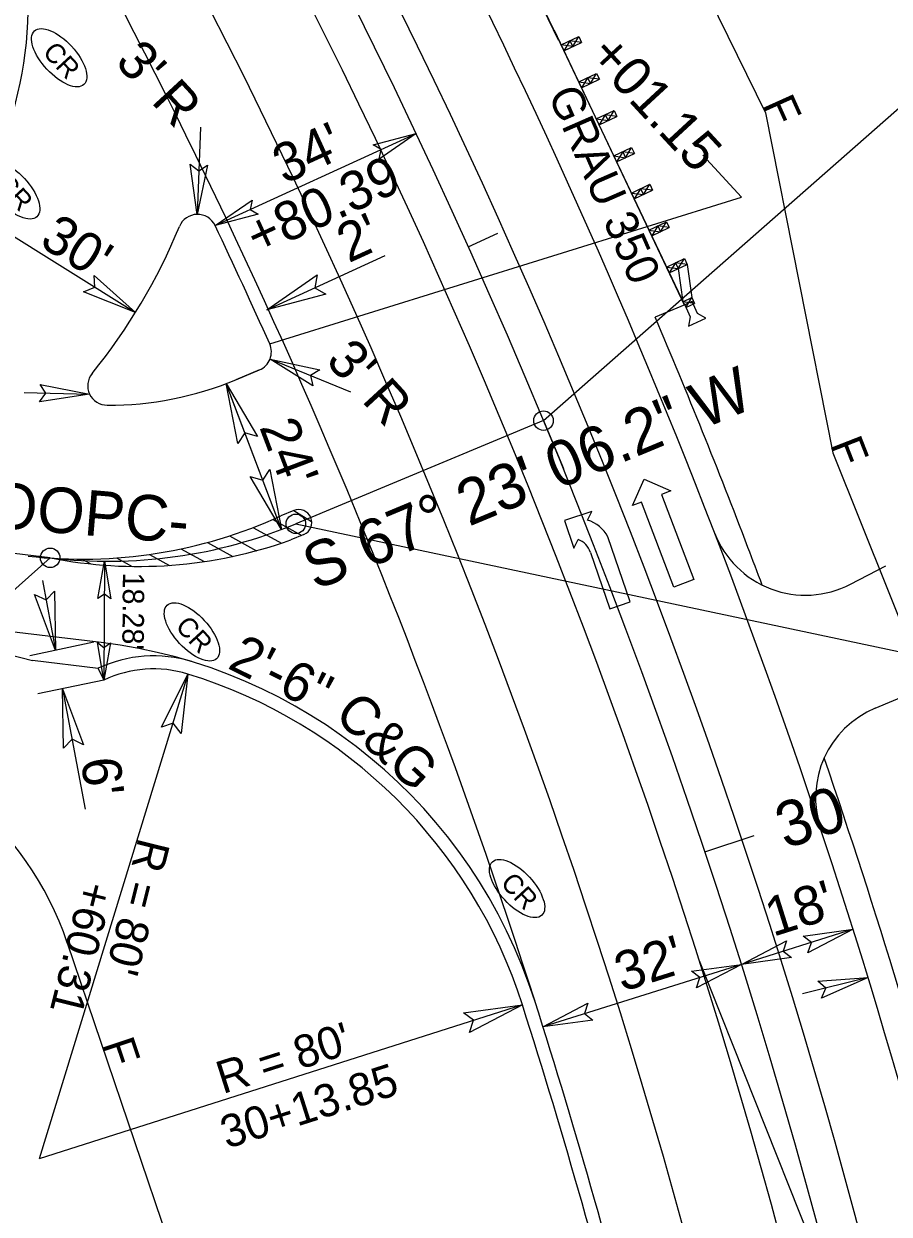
# Model space of a CAD drawing. Extents: x 1702862 to 1704514, y 793768 to 796215.
# Drawn here: x 1703832.7 to 1703965.8, y 794386.1 to 794569.2 of the extents above; entities that cross this region are included whole.
import ezdxf

# ---------------------------------------------------------------- set-up
doc = ezdxf.new("R2010")
doc.units = 0
for name, color, linetype in [('Prop Conc 2ft 6in Curb and Gutter', 7, 'Continuous'), ('Prop Conc 5in Monolithic Surface Mount Island', 7, 'Continuous'), ('Prop Dimension', 7, 'Continuous'), ('Prop Dimension Text', 7, 'Continuous'), ('Prop DSN Text', 7, 'Continuous'), ('Prop EOT', 7, 'Continuous'), ('Prop Guardrail', 7, 'Continuous'), ('Prop Guardrail Anchor Unit CELL', 7, 'Continuous'), ('Prop Horizontal Alignment', 7, 'Continuous'), ('Prop Horizontal Alignment Direction Label', 7, 'Continuous'), ('Prop Horizontal Alignment Station Label', 7, 'Continuous'), ('Prop Horizontal Alignment Tick Label', 7, 'Continuous'), ('Prop Horizontal Alignment Tick Large', 7, 'Continuous'), ('Prop Horizontal Alignment Tick Small', 7, 'Continuous'), ('Prop Lane Arrow CELL', 7, 'Continuous'), ('Prop Lane Lines', 7, 'Continuous'), ('Prop Paint Stripe', 7, 'Continuous'), ('Prop Paved Shoulder', 7, 'Continuous'), ('Prop SS Fill Line', 7, 'Continuous'), ('Prop SS Misc', 7, 'Continuous'), ('Prop SS Transition Line', 7, 'Continuous'), ('Prop Terminator CELL', 7, 'Continuous'), ('Prop WCR CELL', 7, 'Continuous')]:
    doc.layers.add(name, color=color, linetype=linetype)

msp = doc.modelspace()

# ---------------------------------------------------------------- linework, layer by layer
at = {"layer": 'Prop Conc 2ft 6in Curb and Gutter'}
for centre, radius, start, end in [((1703852.67, 794451.95), 18, 72.9584, 115.227), ((1703835.09, 794394.58), 78, 17.697, 72.9584), ((1702989.11, 794124.65), 966, 10.14602, 17.69698)]:
    msp.add_arc(centre, radius, start, end, dxfattribs=at)
at = {"layer": 'Prop Conc 5in Monolithic Surface Mount Island'}
for p, q in [((1703865.32, 794514.43), (1703868.95, 794515.94)), ((1703868.95, 794515.94), (1703865.32, 794514.43))]:
    msp.add_line(p, q, dxfattribs=at)
for centre, radius, start, end in [((1703859.42, 794536.86), 3, 25.344, 157.6692), ((1703859.42, 794536.86), 3, 25.344, 157.6692), ((1703773.4, 794572.2), 90, 320.8717, 337.6692), ((1703773.4, 794572.2), 90, 320.8717, 337.6692), ((1702989.11, 794124.65), 966, 24.15464, 25.34397), ((1702989.11, 794124.65), 966, 24.15464, 25.34397), ((1703867.79, 794518.71), 3, 292.6149, 24.1546), ((1703867.79, 794518.71), 3, 292.6149, 24.1546), ((1703845.54, 794513.51), 3, 140.8717, 269.797), ((1703845.54, 794513.51), 3, 140.8717, 269.797), ((1703845.71, 794561.51), 51, 269.797, 292.6149), ((1703845.71, 794561.51), 51, 269.797, 292.6149)]:
    msp.add_arc(centre, radius, start, end, dxfattribs=at)
at = {"layer": 'Prop Dimension'}
for p, q in [((1703859.91, 794553.27), (1703859.35, 794539.86)), ((1703862.14, 794538.14), (1703893.06, 794552.29)), ((1703824.44, 794540.66), (1703849.88, 794524.75)), ((1703870.07, 794525.2), (1703888.3, 794533.54)), ((1703883.01, 794512.54), (1703870.58, 794517.6)), ((1703872.37, 794491.4), (1703863.84, 794513.84)), ((1703832.77, 794512.44), (1703842.83, 794512.22)), ((1703872.37, 794491.4), (1703864.61, 794511.8)), ((1703845.14, 794486.51), (1703845, 794468.23)), ((1703835.58, 794483.54), (1703837.58, 794472.8)), ((1703843.46, 794474.05), (1703833.63, 794471.98)), ((1703857.95, 794469.16), (1703835.09, 794394.58)), ((1703845, 794468.23), (1703834.87, 794466.1)), ((1703960.26, 794429.91), (1703943.09, 794424.51)), ((1703943.09, 794424.51), (1703912.56, 794414.91)), ((1703962.57, 794422.48), (1703952.5, 794420)), ((1703909.4, 794418.29), (1703835.09, 794394.58))]:
    msp.add_line(p, q, dxfattribs=at)
at = {"layer": 'Prop Dimension Text'}
msp.add_line((1703838.68, 794466.9), (1703842.13, 794448.38), dxfattribs=at)
msp.add_lwpolyline([(1703870.53, 794519.93), (1703943.11, 794542.52), (1703937.18, 794548.94)], dxfattribs=at)
at = {"layer": 'Prop EOT'}
for p, q in [((1703844.62, 794474.01), (1703740.76, 794486.48)), ((1703959.85, 794482.97), (1703965.31, 794485.8)), ((1703844.15, 794470.04), (1703845, 794468.23)), ((1703963.67, 794463.92), (1703974.65, 794468.55))]:
    msp.add_line(p, q, dxfattribs=at)
for centre, radius, start, end in [((1702989.11, 794124.65), 1018, 14.75888, 42.70907), ((1703773.4, 794572.2), 60, 278.4921, 15.5759), ((1703952.94, 794496.29), 15, 201.086, 297.4155), ((1703835.09, 794394.58), 80, 17.697, 83.1536), ((1703852.67, 794451.95), 20, 72.9584, 115.227), ((1703969.5, 794450.1), 15, 112.8746, 198.3644), ((1702989.11, 794124.65), 968, 10.14602, 17.69698)]:
    msp.add_arc(centre, radius, start, end, dxfattribs=at)
at = {"layer": 'Prop Guardrail'}
msp.add_arc((1702988.97, 794124.56), 1026.16, 25.61718, 37.4674, dxfattribs=at)
at = {"layer": 'Prop Guardrail Anchor Unit CELL'}
for p, q in [((1703914.27, 794568.21), (1703934.3, 794525.97)), ((1703915.36, 794565.92), (1703918.07, 794567.2)), ((1703915.36, 794565.92), (1703915.79, 794565.01)), ((1703917.14, 794565.66), (1703915.36, 794565.92)), ((1703916.72, 794566.56), (1703915.79, 794565.01)), ((1703915.79, 794565.01), (1703918.5, 794566.3)), ((1703916.72, 794566.56), (1703917.14, 794565.66)), ((1703918.5, 794566.3), (1703916.72, 794566.56)), ((1703917.14, 794565.66), (1703918.07, 794567.2)), ((1703918.07, 794567.2), (1703918.5, 794566.3)), ((1703915.79, 794565.01), (1703917.14, 794565.66)), ((1703918.06, 794560.22), (1703920.82, 794561.53)), ((1703919.44, 794560.88), (1703918.49, 794559.32)), ((1703918.49, 794559.32), (1703921.25, 794560.63)), ((1703919.44, 794560.88), (1703919.87, 794559.97)), ((1703921.25, 794560.63), (1703919.44, 794560.88)), ((1703919.87, 794559.97), (1703920.82, 794561.53)), ((1703920.82, 794561.53), (1703921.25, 794560.63)), ((1703918.06, 794560.22), (1703919.87, 794559.97)), ((1703920.76, 794554.53), (1703923.51, 794555.83)), ((1703922.14, 794555.18), (1703921.19, 794553.63)), ((1703921.19, 794553.63), (1703923.94, 794554.93)), ((1703922.14, 794555.18), (1703922.57, 794554.28)), ((1703923.94, 794554.93), (1703922.14, 794555.18)), ((1703922.57, 794554.28), (1703923.51, 794555.83)), ((1703923.51, 794555.83), (1703923.94, 794554.93)), ((1703920.76, 794554.53), (1703922.57, 794554.28)), ((1703923.46, 794548.84), (1703926.2, 794550.14)), ((1703924.83, 794549.49), (1703923.89, 794547.93)), ((1703924.83, 794549.49), (1703925.26, 794548.58)), ((1703926.63, 794549.23), (1703924.83, 794549.49)), ((1703925.26, 794548.58), (1703926.2, 794550.14)), ((1703926.2, 794550.14), (1703926.63, 794549.23)), ((1703923.46, 794548.84), (1703923.89, 794547.93)), ((1703923.46, 794548.84), (1703925.26, 794548.58)), ((1703923.89, 794547.93), (1703926.63, 794549.23)), ((1703926.16, 794543.14), (1703928.99, 794544.49)), ((1703927.58, 794543.81), (1703926.59, 794542.24)), ((1703927.58, 794543.81), (1703928.01, 794542.91)), ((1703929.42, 794543.58), (1703927.58, 794543.81)), ((1703928.01, 794542.91), (1703928.99, 794544.49)), ((1703928.99, 794544.49), (1703929.42, 794543.58)), ((1703926.16, 794543.14), (1703928.01, 794542.91)), ((1703926.59, 794542.24), (1703929.42, 794543.58)), ((1703928.86, 794537.45), (1703931.57, 794538.73)), ((1703930.64, 794537.19), (1703931.57, 794538.73)), ((1703931.57, 794538.73), (1703932, 794537.83)), ((1703928.86, 794537.45), (1703930.64, 794537.19)), ((1703930.22, 794538.09), (1703929.29, 794536.54)), ((1703929.29, 794536.54), (1703932, 794537.83)), ((1703930.22, 794538.09), (1703930.64, 794537.19)), ((1703932, 794537.83), (1703930.22, 794538.09)), ((1703931.56, 794531.75), (1703934.33, 794533.07)), ((1703933.37, 794531.51), (1703934.33, 794533.07)), ((1703934.33, 794533.07), (1703934.76, 794532.16)), ((1703931.56, 794531.75), (1703933.37, 794531.51)), ((1703932.94, 794532.41), (1703931.99, 794530.85)), ((1703931.99, 794530.85), (1703934.76, 794532.16)), ((1703932.94, 794532.41), (1703933.37, 794531.51)), ((1703934.76, 794532.16), (1703932.94, 794532.41)), ((1703933.37, 794531.51), (1703934.09, 794526.42)), ((1703934.76, 794532.16), (1703935.44, 794527.07)), ((1703934.09, 794526.42), (1703935.44, 794527.07)), ((1703935.87, 794526.16), (1703934.09, 794526.42)), ((1703934.94, 794526.23), (1703934.38, 794525.97)), ((1703934.38, 794525.97), (1703935.23, 794524.11)), ((1703934.52, 794525.52), (1703935.44, 794527.07)), ((1703934.52, 794525.52), (1703935.87, 794526.16)), ((1703935.5, 794526.48), (1703934.94, 794526.23)), ((1703935.44, 794527.07), (1703935.66, 794526.61)), ((1703935.44, 794527.07), (1703935.87, 794526.16)), ((1703936.34, 794524.61), (1703935.5, 794526.48)), ((1703935.23, 794524.11), (1703934.93, 794522.68)), ((1703934.93, 794522.68), (1703937.61, 794523.89)), ((1703937.61, 794523.89), (1703936.34, 794524.61))]:
    msp.add_line(p, q, dxfattribs=at)
at = {"layer": 'Prop Horizontal Alignment'}
for p, q in [((1703912.65, 794508.14), (1703874.55, 794492.27)), ((1703836.77, 794487.04), (1703719.97, 794501.07))]:
    msp.add_line(p, q, dxfattribs=at)
for centre, radius, start, end in [((1702989.11, 794124.65), 1000, 351.25916, 42.70907), ((1703845.71, 794561.51), 75, 263.1536, 292.6149)]:
    msp.add_arc(centre, radius, start, end, dxfattribs=at)
at = {"layer": 'Prop Horizontal Alignment Station Label'}
for p, q in [((1703912.65, 794508.14), (1704114.85, 794686.06)), ((1703874.55, 794492.27), (1703981.5, 794469.6)), ((1703836.77, 794487.04), (1703754.16, 794413.63))]:
    msp.add_line(p, q, dxfattribs=at)
for centre in [(1703912.65, 794508.14), (1703874.55, 794492.27), (1703836.77, 794487.04)]:
    msp.add_circle(centre, 1.5, dxfattribs=at)
at = {"layer": 'Prop Horizontal Alignment Tick Large'}
for p, q in [((1703912.65, 794508.14), (1703915.73, 794500.76)), ((1703937.48, 794441.8), (1703945.07, 794444.34))]:
    msp.add_line(p, q, dxfattribs=at)
at = {"layer": 'Prop Horizontal Alignment Tick Small'}
msp.add_line((1703901.08, 794534.89), (1703905.64, 794536.95), dxfattribs=at)
at = {"layer": 'Prop Lane Arrow CELL'}
for p, q in [((1703926.33, 794495.09), (1703928.11, 794499.13)), ((1703928.11, 794499.13), (1703932.22, 794497.32)), ((1703932.22, 794497.32), (1703930.82, 794496.79)), ((1703930.82, 794496.79), (1703935.76, 794483.69)), ((1703927.73, 794495.62), (1703926.33, 794495.09)), ((1703932.68, 794482.52), (1703927.73, 794495.62)), ((1703920.08, 794494.17), (1703915.9, 794492.78)), ((1703915.9, 794492.78), (1703917.32, 794488.51)), ((1703919.43, 794492.83), (1703920.08, 794494.17)), ((1703917.32, 794488.51), (1703917.97, 794489.85)), ((1703925.96, 794480.27), (1703922.53, 794490.25)), ((1703919.87, 794487.86), (1703922.84, 794479.2)), ((1703935.76, 794483.69), (1703932.68, 794482.52)), ((1703922.84, 794479.2), (1703925.96, 794480.27))]:
    msp.add_line(p, q, dxfattribs=at)
for centre, radius, start, end in [((1703917.9, 794487.82), 5.25, 27.6389, 72.9506), ((1703916.78, 794486.81), 3.28, 18.9628, 68.621)]:
    msp.add_arc(centre, radius, start, end, dxfattribs=at)
at = {"layer": 'Prop Lane Lines'}
msp.add_line((1703973.28, 794333.07), (1703936.62, 794425.07), dxfattribs=at)
for radius, start, end in [(1006, 0.00687, 42.70907), (994, 359.40932, 42.70907), (980, 359.40932, 42.70907), (968, 17.6382, 31.00789)]:
    msp.add_arc((1702989.11, 794124.65), radius, start, end, dxfattribs=at)
at = {"layer": 'Prop Paint Stripe'}
for p, q in [((1703871.02, 794492.91), (1703875.45, 794490.48)), ((1703874.23, 794494.3), (1703872.25, 794493.48)), ((1703874.22, 794494.3), (1703876.98, 794492.64)), ((1703868.04, 794491.64), (1703872.33, 794489.28)), ((1703860.95, 794489.4), (1703864.87, 794487.25)), ((1703864.36, 794490.41), (1703868.51, 794488.13)), ((1703875.77, 794490.61), (1703873.79, 794489.79)), ((1703846.99, 794487.02), (1703849.37, 794485.72)), ((1703852.02, 794487.56), (1703855.1, 794485.87)), ((1703856.86, 794488.42), (1703860.44, 794486.45)), ((1703841.67, 794486.83), (1703843, 794486.1))]:
    msp.add_line(p, q, dxfattribs=at)
for centre, radius, start, end in [((1703875, 794492.46), 2, 22.6149, 112.6149), ((1703841.63, 794560.61), 73.78, 263.5676, 294.5181), ((1703875, 794492.46), 2, 292.6149, 22.6149), ((1703850.32, 794555.26), 69.55, 258.7681, 289.7186)]:
    msp.add_arc(centre, radius, start, end, dxfattribs=at)
at = {"layer": 'Prop Paved Shoulder'}
for p, q in [((1703914.93, 794566.65), (1703909.49, 794578.04)), ((1703914.26, 794568.23), (1703934.31, 794525.94)), ((1703934.38, 794525.97), (1703929.83, 794524.06)), ((1703803.86, 794478.91), (1703834.03, 794471.26)), ((1703844.15, 794470.04), (1703834.03, 794471.26))]:
    msp.add_line(p, q, dxfattribs=at)
for start, end in [(20.86475, 23.00509), (20.51732, 20.86475), (14.75888, 18.93305)]:
    msp.add_arc((1702989.11, 794124.65), 1022, start, end, dxfattribs=at)
at = {"layer": 'Prop SS Fill Line'}
for p, q in [((1703923.62, 794602.55), (1703946.81, 794555.47)), ((1703946.81, 794555.47), (1703957.17, 794503.16)), ((1703839.4, 794427.8), (1703859.6, 794368.12))]:
    msp.add_line(p, q, dxfattribs=at)
msp.add_arc((1703792.04, 794411.78), 50, 18.6944, 82.73, dxfattribs=at)
at = {"layer": 'Prop SS Transition Line'}
msp.add_line((1703957.17, 794503.16), (1703976.48, 794454.84), dxfattribs=at)
at = {"layer": 'Prop Terminator CELL'}
for points in [[(1703886.44, 794550.54), (1703893.06, 794552.29), (1703887.39, 794548.37), (1703887.67, 794549.82)], [(1703860.98, 794547.45), (1703859.35, 794539.86), (1703858.31, 794547.6), (1703859.63, 794546.57)], [(1703868.76, 794539.89), (1703862.14, 794538.14), (1703867.81, 794542.06), (1703867.52, 794540.61)], [(1703843.51, 794530.44), (1703849.88, 794524.75), (1703841.91, 794527.97), (1703843.61, 794528.66)], [(1703879.15, 794527.6), (1703870.07, 794525.2), (1703877.85, 794530.57), (1703877.46, 794528.58)], [(1703877.17, 794513.5), (1703870.58, 794517.6), (1703878.22, 794515.96), (1703876.8, 794515.07)], [(1703835.21, 794513.7), (1703842.83, 794512.22), (1703835.11, 794511.03), (1703836.12, 794512.37)], [(1703865.64, 794504.62), (1703863.84, 794513.84), (1703868.68, 794505.72), (1703866.73, 794506.24)], [(1703870.57, 794500.62), (1703872.37, 794491.4), (1703867.52, 794499.52), (1703869.48, 794499)], [(1703844.11, 794480.78), (1703845.14, 794486.51), (1703846.12, 794480.73), (1703845.1, 794481.47)], [(1703837.45, 794481.93), (1703837.58, 794472.8), (1703834.35, 794481.41), (1703836.13, 794480.57)], [(1703846.03, 794473.96), (1703845, 794468.23), (1703844.02, 794474.01), (1703845.04, 794473.27)], [(1703853.88, 794460.98), (1703857.95, 794469.16), (1703856.89, 794460.03), (1703855.68, 794461.59)], [(1703838.81, 794457.77), (1703838.68, 794466.9), (1703841.91, 794458.3), (1703840.13, 794459.14)], [(1703952.57, 794428.87), (1703960.26, 794429.91), (1703953.33, 794426.3), (1703953.86, 794427.89)], [(1703950.78, 794425.55), (1703943.09, 794424.51), (1703950.02, 794428.11), (1703949.5, 794426.52)], [(1703935.4, 794423.47), (1703943.09, 794424.51), (1703936.16, 794420.91), (1703936.69, 794422.5)], [(1703954.82, 794421.93), (1703962.57, 794422.48), (1703955.42, 794419.32), (1703956.05, 794420.87)], [(1703900.35, 794417.06), (1703909.4, 794418.29), (1703901.25, 794414.04), (1703901.86, 794415.91)], [(1703920.26, 794415.95), (1703912.56, 794414.91), (1703919.49, 794418.52), (1703918.97, 794416.93)]]:
    msp.add_lwpolyline(points, close=True, dxfattribs=at)
at = {"layer": 'Prop WCR CELL'}
for centre in [(1703838.15, 794563.95), (1703830.91, 794543.62), (1703858.57, 794475.64), (1703908.58, 794436.18)]:
    msp.add_ellipse(centre, major_axis=(3.8, -4.12), ratio=0.462467, dxfattribs=at)

# ---------------------------------------------------------------- texts
at = {"layer": 'Prop Dimension Text'}
for s, height, rotation, p in [("3' R", 6, 312.7091, (1703846.58, 794563.18)), ('+01.15', 6, 312.7091, (1703919.35, 794564.15)), ("30'", 6, 327.9676, (1703834.89, 794535.16)), ("3' R", 6, 312.7091, (1703878.97, 794517.21)), ("24'", 6, 290.8182, (1703868.89, 794507.17)), ("18.28'", 3.3, 269.5618, (1703847.95, 794484.78)), ('2\'-6"  ', 6, 333.7051, (1703863.86, 794470.13)), (' C&G', 6, 316.9422, (1703878.61, 794464.12)), ("6'", 6, 277.2204, (1703841.5, 794456.01)), ("R = 80'", 5, 256.066, (1703850.38, 794444.15)), ('+60.31', 5, 256.066, (1703841.68, 794437.55)), ("18'", 6, 17.4494, (1703947.94, 794428.73)), ("32'", 6, 17.4494, (1703924.75, 794420.26)), ("R = 80'", 5, 17.6451, (1703863.31, 794404.55)), ('30+13.85', 5, 17.6451, (1703863.94, 794396.12))]:
    msp.add_text(s, height=height, rotation=rotation, dxfattribs=at).set_placement(p)
at = {"layer": 'Prop DSN Text'}
for s, p in [("34'", (1703872.79, 794544.44)), ('+80.39', (1703868.65, 794533.39)), ("2'", (1703882.67, 794532.33))]:
    msp.add_text(s, height=6, rotation=24.5769, dxfattribs=at).set_placement(p)
at = {"layer": 'Prop Guardrail Anchor Unit CELL'}
msp.add_text('GRAU 350', height=5, rotation=293.6393, dxfattribs=at).set_placement((1703913.27, 794558.31))
at = {"layer": 'Prop Horizontal Alignment Direction Label'}
for s, rotation, p in [('S 67%%d 23\' 06.2" W', 22.6149, (1703877.54, 794481.97)), ('-LOOPC-', 355.1313, (1703818.98, 794492.49))]:
    msp.add_text(s, height=7, rotation=rotation, dxfattribs=at).set_placement(p)
at = {"layer": 'Prop Horizontal Alignment Tick Label'}
msp.add_text('30', height=7, rotation=18.4908, dxfattribs=at).set_placement((1703949.82, 794442.22))
at = {"layer": 'Prop SS Misc'}
for rotation, p in [(294.2204, (1703946.23, 794556.76)), (291.3556, (1703956.65, 794504.48)), (288.4908, (1703844.67, 794412.25))]:
    msp.add_text('F', height=5, rotation=rotation, dxfattribs=at).set_placement(p)
at = {"layer": 'Prop WCR CELL'}
for p in [(1703835.47, 794564.68), (1703828.22, 794544.35), (1703855.88, 794476.37), (1703905.9, 794436.91)]:
    msp.add_text('CR', height=3, rotation=312.7091, dxfattribs=at).set_placement(p)

doc.saveas('drawing.dxf')
